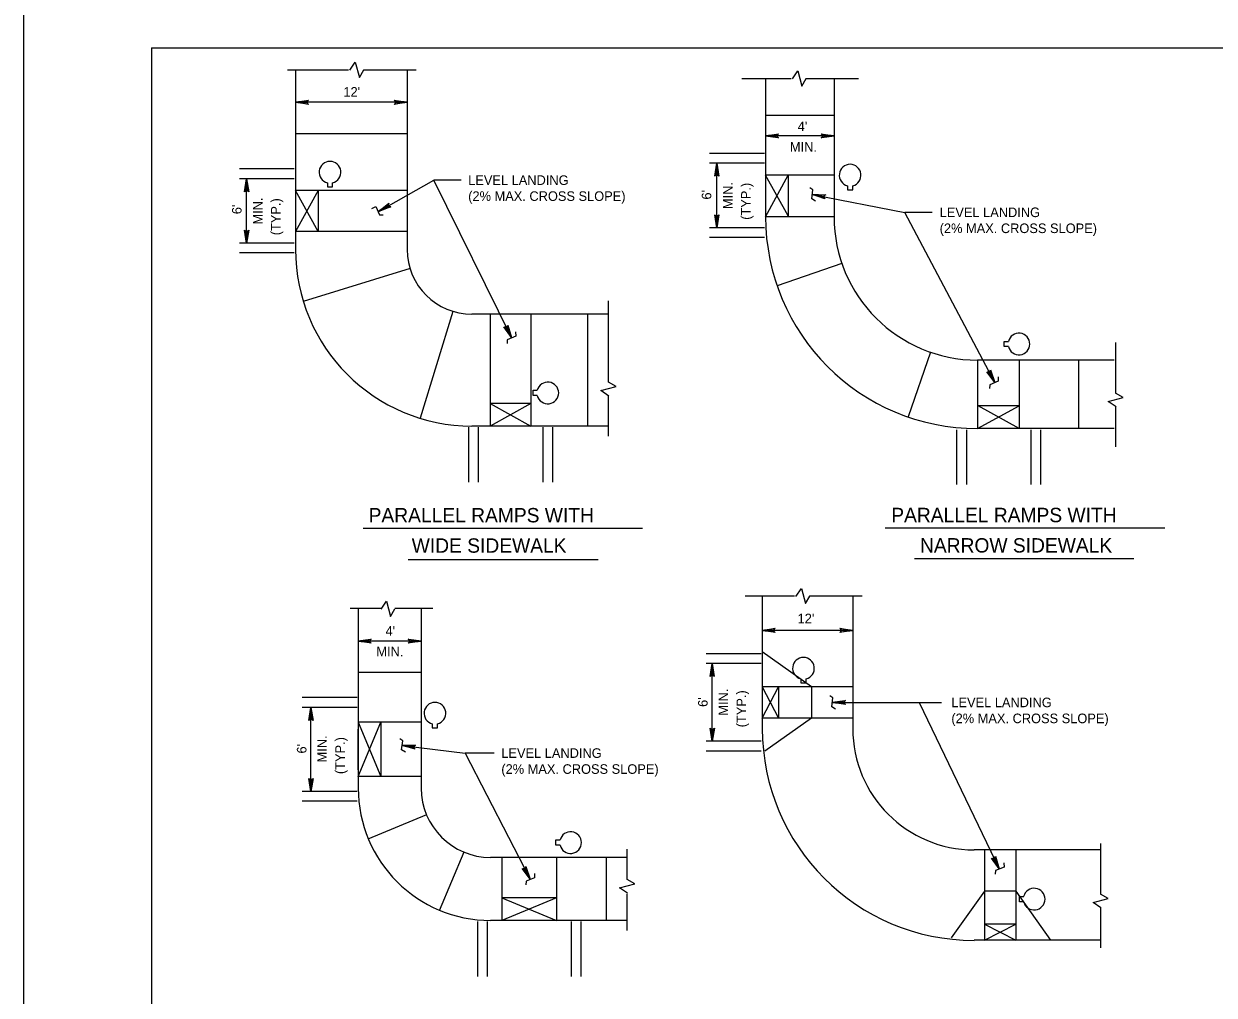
# Model space of a CAD drawing. Extents: x 36 to 940, y -1166 to 1210.
# Drawn here: x 35.9 to 408.6, y -883.4 to -579.3 of the extents above; entities that cross this region are included whole.
import ezdxf

# ---------------------------------------------------------------- set-up
doc = ezdxf.new("R2010")
doc.units = 0
for name, color, linetype in [('1', 7, 'Continuous'), ('2', 7, 'Continuous'), ('PLT-BNDY', 7, 'Continuous')]:
    doc.layers.add(name, color=color, linetype=linetype)

msp = doc.modelspace()

# ---------------------------------------------------------------- linework, layer by layer
at = {"layer": '1'}
for q in [(861.86, -586.83), (75.86, -1150.83)]:
    msp.add_line((75.86, -586.83), q, dxfattribs=at)
at = {"layer": '2'}
for p, q in [((137.56, -593.83), (118.38, -593.83)), ((120.93, -593.83), (120.93, -649.98)), ((158.71, -593.83), (142.18, -593.83)), ((155.93, -593.83), (155.93, -649.98)), ((276.13, -596.52), (260.66, -596.52)), ((268.14, -596.52), (268.14, -639.72)), ((297.29, -596.52), (280.76, -596.52)), ((289.58, -596.52), (289.58, -639.72)), ((155.93, -603.89), (120.93, -603.89)), ((289.58, -608.01), (268.14, -608.01)), ((155.93, -613.81), (120.93, -613.81)), ((289.58, -614.42), (268.14, -614.42)), ((267.77, -619.92), (250.6, -619.92)), ((120.56, -624.76), (103.39, -624.76)), ((267.77, -622.99), (250.6, -622.99)), ((252.86, -643.15), (252.86, -622.99)), ((120.56, -627.83), (103.39, -627.83)), ((105.64, -647.99), (105.64, -627.83)), ((130.91, -629.09), (130.91, -630.39)), ((132.56, -630.39), (132.56, -629.09)), ((146.96, -638.06), (164.24, -628.3)), ((172.85, -628.3), (164.24, -628.3)), ((188.6, -677.56), (164.24, -628.3)), ((289.58, -626.68), (268.14, -626.68)), ((275.22, -639.46), (268.14, -626.68)), ((268.14, -639.72), (275.22, -626.68)), ((275.22, -626.68), (275.22, -639.46)), ((155.93, -631.52), (120.93, -631.52)), ((128.01, -644.3), (120.93, -631.52)), ((128.01, -631.52), (120.93, -644.3)), ((128.01, -631.52), (128.01, -644.3)), ((130.91, -630.39), (132.56, -630.39)), ((282.85, -632.72), (311.73, -638.36)), ((293.79, -630), (293.79, -631.3)), ((293.79, -631.3), (295.45, -631.3)), ((295.45, -631.3), (295.45, -630)), ((289.58, -639.72), (268.14, -639.72)), ((320.33, -638.36), (311.73, -638.36)), ((339.89, -691.59), (311.73, -638.36)), ((155.93, -644.3), (120.93, -644.3)), ((267.77, -643.15), (250.6, -643.15)), ((120.56, -647.99), (103.39, -647.99)), ((267.77, -646.22), (250.6, -646.22)), ((120.56, -651.06), (103.39, -651.06)), ((156.83, -655.94), (123.37, -666.22)), ((292.05, -654.38), (271.78, -661.39)), ((219, -691.48), (219, -666.08)), ((170.24, -669.35), (159.96, -702.81)), ((219, -670.25), (176.2, -670.25)), ((181.88, -670.25), (181.88, -705.25)), ((194.66, -670.25), (194.66, -705.25)), ((212.37, -670.25), (212.37, -705.25)), ((319.81, -682.14), (312.8, -702.41)), ((342.89, -680.4), (342.89, -678.74)), ((342.89, -678.74), (344.19, -678.74)), ((344.19, -680.4), (342.89, -680.4)), ((377.8, -694.86), (377.8, -679.05)), ((377.26, -684.61), (334.47, -684.61)), ((334.47, -684.61), (334.47, -706.05)), ((347.51, -684.61), (347.51, -706.05)), ((366.18, -684.61), (366.18, -706.05)), ((195.35, -695.71), (195.35, -694.06)), ((195.35, -694.06), (196.65, -694.06)), ((196.65, -695.71), (195.35, -695.71)), ((219, -708.39), (219, -695.72)), ((194.66, -698.17), (181.88, -698.17)), ((181.88, -698.17), (194.66, -705.25)), ((194.66, -698.17), (181.88, -705.25)), ((334.47, -706.05), (347.51, -698.97)), ((347.51, -698.97), (334.73, -698.97)), ((347.51, -706.05), (334.73, -698.97)), ((377.8, -711.78), (377.8, -699.11)), ((175.12, -705.62), (175.12, -722.79)), ((219, -705.25), (176.2, -705.25)), ((178.19, -705.62), (178.19, -722.79)), ((198.35, -705.62), (198.35, -722.79)), ((201.42, -705.62), (201.42, -722.79)), ((327.97, -706.42), (327.97, -723.59)), ((331.04, -706.42), (331.04, -723.59)), ((377.26, -706.05), (334.47, -706.05)), ((351.2, -706.42), (351.2, -723.59)), ((354.27, -706.42), (354.27, -723.59)), ((142.08, -737.23), (229.65, -737.23)), ((393.13, -737.23), (305.56, -737.23)), ((156.19, -747.05), (215.73, -747.05)), ((383.51, -746.84), (314.76, -746.84)), ((277.23, -758.55), (261.76, -758.55)), ((267.1, -758.55), (267.1, -799.93)), ((298.38, -758.55), (281.86, -758.55)), ((295.43, -758.55), (295.43, -799.93)), ((147.98, -762.42), (138.03, -762.42)), ((140.57, -762.42), (140.57, -818.57)), ((163.99, -762.42), (152, -762.42)), ((160.29, -762.42), (160.29, -818.57)), ((295.43, -769.22), (267.1, -769.22)), ((160.29, -772.57), (140.57, -772.57)), ((266.74, -776.55), (249.57, -776.55)), ((282.55, -786.88), (267.1, -775.94)), ((160.29, -782.4), (140.57, -782.4)), ((266.74, -779.62), (249.57, -779.62)), ((251.45, -803.93), (251.45, -779.62)), ((279.18, -784.39), (279.18, -785.69)), ((279.18, -785.69), (280.83, -785.69)), ((280.83, -785.69), (280.83, -784.39)), ((295.43, -786.88), (267.1, -786.88)), ((267.1, -786.88), (272.17, -796.67)), ((267.1, -796.67), (272.17, -786.88)), ((272.17, -786.88), (272.17, -796.67)), ((282.55, -786.88), (282.55, -796.67)), ((140.21, -790.28), (123.04, -790.28)), ((140.21, -793.35), (123.04, -793.35)), ((125.78, -819.65), (125.78, -793.35)), ((289.1, -791.78), (323.27, -791.78)), ((316.27, -791.78), (341.26, -843.87)), ((295.43, -796.67), (267.1, -796.67)), ((282.55, -796.67), (267.9, -807.04)), ((160.29, -797.98), (140.57, -797.98)), ((140.57, -797.98), (147.65, -815.01)), ((140.57, -815.01), (147.65, -797.98)), ((140.57, -812.89), (140.57, -800.11)), ((147.65, -797.98), (147.65, -815.01)), ((163.78, -798.46), (163.78, -799.76)), ((163.78, -799.76), (165.43, -799.76)), ((165.43, -799.76), (165.43, -798.46)), ((266.74, -803.93), (249.57, -803.93)), ((154.43, -805.29), (174.05, -807.65)), ((183.17, -807.65), (174.05, -807.65)), ((174.05, -807.65), (194.39, -847.08)), ((266.74, -807), (249.57, -807)), ((160.29, -815.01), (140.57, -815.01)), ((140.21, -819.65), (123.04, -819.65)), ((140.21, -822.72), (123.04, -822.72)), ((161.98, -826.95), (143.61, -834.63)), ((202.47, -836.48), (202.47, -834.83)), ((202.47, -834.83), (203.77, -834.83)), ((173.64, -838.62), (165.97, -856.99)), ((203.77, -836.48), (202.47, -836.48)), ((224.83, -847.16), (224.83, -837.7)), ((373.1, -837.92), (333.43, -837.92)), ((336.68, -837.92), (336.68, -866.25)), ((346.47, -837.92), (346.47, -866.25)), ((373.1, -851.71), (373.1, -835.9)), ((224.83, -840.3), (182.03, -840.3)), ((185.58, -840.3), (185.58, -860.02)), ((202.62, -840.3), (202.62, -860.02)), ((218.2, -840.3), (218.2, -860.02)), ((202.62, -852.95), (185.58, -852.95)), ((185.58, -852.95), (202.62, -860.02)), ((202.62, -852.95), (185.58, -860.02)), ((224.83, -863.17), (224.83, -851.7)), ((336.68, -850.81), (326.31, -865.45)), ((346.47, -850.81), (336.68, -850.81)), ((346.47, -850.81), (357.41, -866.25)), ((347.67, -854.18), (347.67, -852.52)), ((347.67, -852.52), (348.97, -852.52)), ((348.97, -854.18), (347.67, -854.18)), ((373.1, -868.63), (373.1, -855.95)), ((177.88, -860.39), (177.88, -877.56)), ((180.95, -860.39), (180.95, -877.56)), ((224.83, -860.02), (182.03, -860.02)), ((207.25, -860.39), (207.25, -877.56)), ((210.32, -860.39), (210.32, -877.56)), ((346.47, -861.18), (336.68, -861.18)), ((336.68, -861.18), (346.47, -866.25)), ((336.68, -866.25), (346.47, -861.18)), ((373.1, -866.25), (333.43, -866.25))]:
    msp.add_line(p, q, dxfattribs=at)
for points in [[(137.98, -593.86), (139.67, -591.38), (140.93, -596.12), (142.29, -593.75)], [(276.56, -596.54), (278.24, -594.06), (279.51, -598.8), (280.86, -596.43)], [(124.79, -604.38), (124.65, -604.1), (120.93, -603.89), (124.79, -604.38), (124.99, -604.55), (120.93, -603.89), (124.64, -603.71), (124.78, -603.43), (120.93, -603.89), (124.99, -603.25), (124.78, -603.43)], [(152.07, -603.41), (152.22, -603.69), (155.93, -603.89), (152.07, -603.41), (151.87, -603.24), (155.93, -603.89), (152.22, -604.08), (152.08, -604.35), (155.93, -603.89), (151.87, -604.54), (152.08, -604.35)], [(272, -614.9), (271.86, -614.62), (268.14, -614.42), (272, -614.9), (272.2, -615.07), (268.14, -614.42), (271.85, -614.23), (271.99, -613.96), (268.14, -614.42), (272.2, -613.77), (271.99, -613.96)], [(285.72, -613.93), (285.87, -614.21), (289.58, -614.42), (285.72, -613.93), (285.53, -613.76), (289.58, -614.42), (285.87, -614.6), (285.74, -614.88), (289.58, -614.42), (285.53, -615.06), (285.74, -614.88)], [(252.37, -626.85), (252.65, -626.71), (252.86, -622.99), (252.37, -626.85), (252.2, -627.05), (252.86, -622.99), (253.04, -626.7), (253.32, -626.84), (252.86, -622.99), (253.5, -627.05), (253.32, -626.84)], [(105.16, -631.69), (105.44, -631.54), (105.64, -627.83), (105.16, -631.69), (104.99, -631.89), (105.64, -627.83), (105.83, -631.54), (106.1, -631.68), (105.64, -627.83), (106.29, -631.89), (106.1, -631.68)], [(283.82, -634.8), (282.6, -634.11), (282.96, -631.27), (282.02, -630.63)], [(286.55, -633.93), (286.46, -633.63), (282.85, -632.72), (286.55, -633.93), (286.71, -634.14), (282.85, -632.72), (286.53, -633.25), (286.72, -633), (282.85, -632.72), (286.96, -632.86), (286.72, -633)], [(144.82, -637.11), (146.05, -636.49), (147.29, -639.08), (148.43, -639.11)], [(150.56, -636.58), (150.3, -636.41), (146.96, -638.06), (150.56, -636.58), (150.82, -636.63), (146.96, -638.06), (150.1, -636.07), (150.09, -635.76), (146.96, -638.06), (150.18, -635.5), (150.09, -635.76)], [(253.34, -639.29), (253.06, -639.43), (252.86, -643.15), (253.34, -639.29), (253.51, -639.09), (252.86, -643.15), (252.67, -639.44), (252.4, -639.3), (252.86, -643.15), (252.21, -639.09), (252.4, -639.3)], [(106.13, -644.13), (105.85, -644.27), (105.64, -647.99), (106.13, -644.13), (106.3, -643.93), (105.64, -647.99), (105.46, -644.27), (105.18, -644.14), (105.64, -647.99), (105, -643.93), (105.18, -644.14)], [(187.32, -673.88), (187.13, -674.14), (188.6, -677.56), (187.32, -673.88), (187.39, -673.63), (188.6, -677.56), (186.79, -674.31), (186.48, -674.31), (188.6, -677.56), (186.22, -674.21), (186.48, -674.31)], [(189.87, -675.78), (189.92, -677.13), (187.27, -678.23), (187.18, -679.37)], [(338.51, -687.95), (338.33, -688.21), (339.89, -691.59), (338.51, -687.95), (338.57, -687.7), (339.89, -691.59), (337.99, -688.39), (337.68, -688.4), (339.89, -691.59), (337.42, -688.3), (337.68, -688.4)], [(219.08, -695.85), (216.6, -694.16), (221.34, -692.9), (218.97, -691.54)], [(340.94, -689.89), (340.98, -691.24), (338.34, -692.34), (338.25, -693.47)], [(377.88, -699.23), (375.4, -697.55), (380.14, -696.28), (377.77, -694.92)], [(277.65, -758.58), (279.34, -756.1), (280.6, -760.83), (281.96, -758.47)], [(147.77, -762.58), (149.46, -760.1), (150.72, -764.84), (152.08, -762.47)], [(270.96, -769.7), (270.82, -769.42), (267.1, -769.22), (270.96, -769.7), (271.16, -769.87), (267.1, -769.22), (270.82, -769.03), (270.95, -768.76), (267.1, -769.22), (271.16, -768.57), (270.95, -768.76)], [(291.57, -768.73), (291.72, -769.01), (295.43, -769.22), (291.57, -768.73), (291.37, -768.56), (295.43, -769.22), (291.72, -769.4), (291.58, -769.68), (295.43, -769.22), (291.37, -769.86), (291.58, -769.68)], [(144.43, -773.06), (144.29, -772.78), (140.57, -772.57), (144.43, -773.06), (144.63, -773.23), (140.57, -772.57), (144.29, -772.39), (144.42, -772.11), (140.57, -772.57), (144.63, -771.93), (144.42, -772.11)], [(156.43, -772.09), (156.58, -772.37), (160.29, -772.57), (156.43, -772.09), (156.24, -771.92), (160.29, -772.57), (156.58, -772.76), (156.45, -773.03), (160.29, -772.57), (156.24, -773.22), (156.45, -773.03)], [(250.96, -783.48), (251.24, -783.34), (251.45, -779.62), (250.96, -783.48), (250.79, -783.68), (251.45, -779.62), (251.63, -783.33), (251.91, -783.47), (251.45, -779.62), (252.09, -783.68), (251.91, -783.47)], [(290.09, -793.87), (288.87, -793.18), (289.23, -790.34), (288.29, -789.7)], [(125.29, -797.21), (125.57, -797.06), (125.78, -793.35), (125.29, -797.21), (125.12, -797.41), (125.78, -793.35), (125.96, -797.06), (126.24, -797.2), (125.78, -793.35), (126.42, -797.41), (126.24, -797.2)], [(292.96, -792.26), (292.82, -791.98), (289.1, -791.78), (292.96, -792.26), (293.16, -792.43), (289.1, -791.78), (292.82, -791.59), (292.95, -791.32), (289.1, -791.78), (293.16, -791.13), (292.95, -791.32)], [(251.93, -800.07), (251.65, -800.21), (251.45, -803.93), (251.93, -800.07), (252.1, -799.87), (251.45, -803.93), (251.26, -800.22), (250.99, -800.08), (251.45, -803.93), (250.8, -799.87), (250.99, -800.08)], [(155.4, -807.3), (154.18, -806.6), (154.54, -803.76), (153.6, -803.12)], [(158.21, -806.23), (158.1, -805.94), (154.43, -805.29), (158.21, -806.23), (158.38, -806.42), (154.43, -805.29), (158.14, -805.55), (158.31, -805.29), (154.43, -805.29), (158.54, -805.13), (158.31, -805.29)], [(126.26, -815.79), (125.98, -815.93), (125.78, -819.65), (126.26, -815.79), (126.43, -815.59), (125.78, -819.65), (125.59, -815.93), (125.32, -815.8), (125.78, -819.65), (125.13, -815.59), (125.32, -815.8)], [(340.03, -840.18), (339.84, -840.44), (341.26, -843.87), (340.03, -840.18), (340.1, -839.93), (341.26, -843.87), (339.49, -840.61), (339.18, -840.6), (341.26, -843.87), (338.93, -840.49), (339.18, -840.6)], [(342.77, -841.95), (342.81, -843.3), (340.17, -844.4), (340.08, -845.53)], [(193.05, -843.42), (192.87, -843.68), (194.39, -847.08), (193.05, -843.42), (193.11, -843.17), (194.39, -847.08), (192.53, -843.86), (192.22, -843.87), (194.39, -847.08), (191.96, -843.77), (192.22, -843.87)], [(195.74, -845.3), (195.79, -846.65), (193.14, -847.75), (193.05, -848.89)], [(224.9, -851.53), (222.43, -849.84), (227.16, -848.58), (224.79, -847.22)], [(373.18, -856.08), (370.7, -854.39), (375.44, -853.13), (373.07, -851.77)]]:
    msp.add_lwpolyline(points, dxfattribs=at)
for centre, radius, start, end in [((131.74, -625.79), 3.4, 284.1014, 255.8986), ((294.62, -626.71), 3.4, 284.1014, 255.8986), ((334.47, -639.72), 66.33, 180, 270), ((334.47, -639.72), 44.88, 180, 270), ((176.2, -649.98), 55.27, 180, 270), ((176.2, -649.98), 20.27, 180, 270), ((347.48, -679.57), 3.4, 194.1014, 165.8986), ((199.95, -694.89), 3.4, 194.1014, 165.8986), ((280.01, -781.09), 3.4, 284.1014, 255.8986), ((164.6, -795.16), 3.4, 284.1014, 255.8986), ((333.43, -799.93), 66.33, 180, 270), ((333.43, -799.93), 38, 180, 270), ((182.03, -818.57), 41.45, 180, 270), ((182.03, -818.57), 21.73, 180, 270), ((207.07, -835.66), 3.4, 194.1014, 165.8986), ((352.26, -853.35), 3.4, 194.1014, 165.8986)]:
    msp.add_arc(centre, radius, start, end, dxfattribs=at)
at = {"layer": 'PLT-BNDY'}
msp.add_lwpolyline([(35.86, -571.83), (876.86, -571.83), (876.86, -1165.83), (35.86, -1165.83)], close=True, dxfattribs=at)

# ---------------------------------------------------------------- texts
at = {"layer": '2'}
for s, height, p in [("12'", 3, (135.94, -602.14)), ("4'", 3, (278.2, -612.93)), ('MIN.', 3, (275.76, -619.36)), ('LEVEL LANDING', 3, (175.02, -629.77)), ('(2% MAX. CROSS SLOPE)', 3, (175.02, -634.77)), ('LEVEL LANDING', 3, (322.66, -639.84)), ('(2% MAX. CROSS SLOPE)', 3, (322.66, -644.84)), ('PARALLEL RAMPS WITH', 4.5, (143.83, -735.41)), ('PARALLEL RAMPS WITH', 4.5, (307.5, -735.35)), ('WIDE SIDEWALK', 4.5, (157.33, -744.91)), ('NARROW SIDEWALK', 4.5, (316.5, -744.85)), ("12'", 3, (278.17, -766.98)), ("4'", 3, (149.14, -770.9)), ('MIN.', 3, (146.26, -777.36)), ('LEVEL LANDING', 3, (326.32, -793.27)), ('(2% MAX. CROSS SLOPE)', 3, (326.32, -798.27)), ('LEVEL LANDING', 3, (185.39, -809.13)), ('(2% MAX. CROSS SLOPE)', 3, (185.39, -814.13))]:
    msp.add_text(s, height=height, dxfattribs=at).set_placement(p)
for s, p in [('MIN.', (257.82, -637.34)), ('(TYP.)', (263.47, -640.69)), ("6'", (251.15, -634.35)), ("6'", (104.05, -638.93)), ('MIN.', (110.61, -642.17)), ('(TYP.)', (116.25, -645.53)), ('MIN.', (256.42, -795.91)), ('(TYP.)', (262.06, -799.57)), ("6'", (250, -793.18)), ("6'", (124.37, -807.77)), ('MIN.', (130.74, -810.55)), ('(TYP.)', (136.39, -814.21))]:
    msp.add_text(s, height=3, rotation=90, dxfattribs=at).set_placement(p)

doc.saveas('drawing.dxf')
